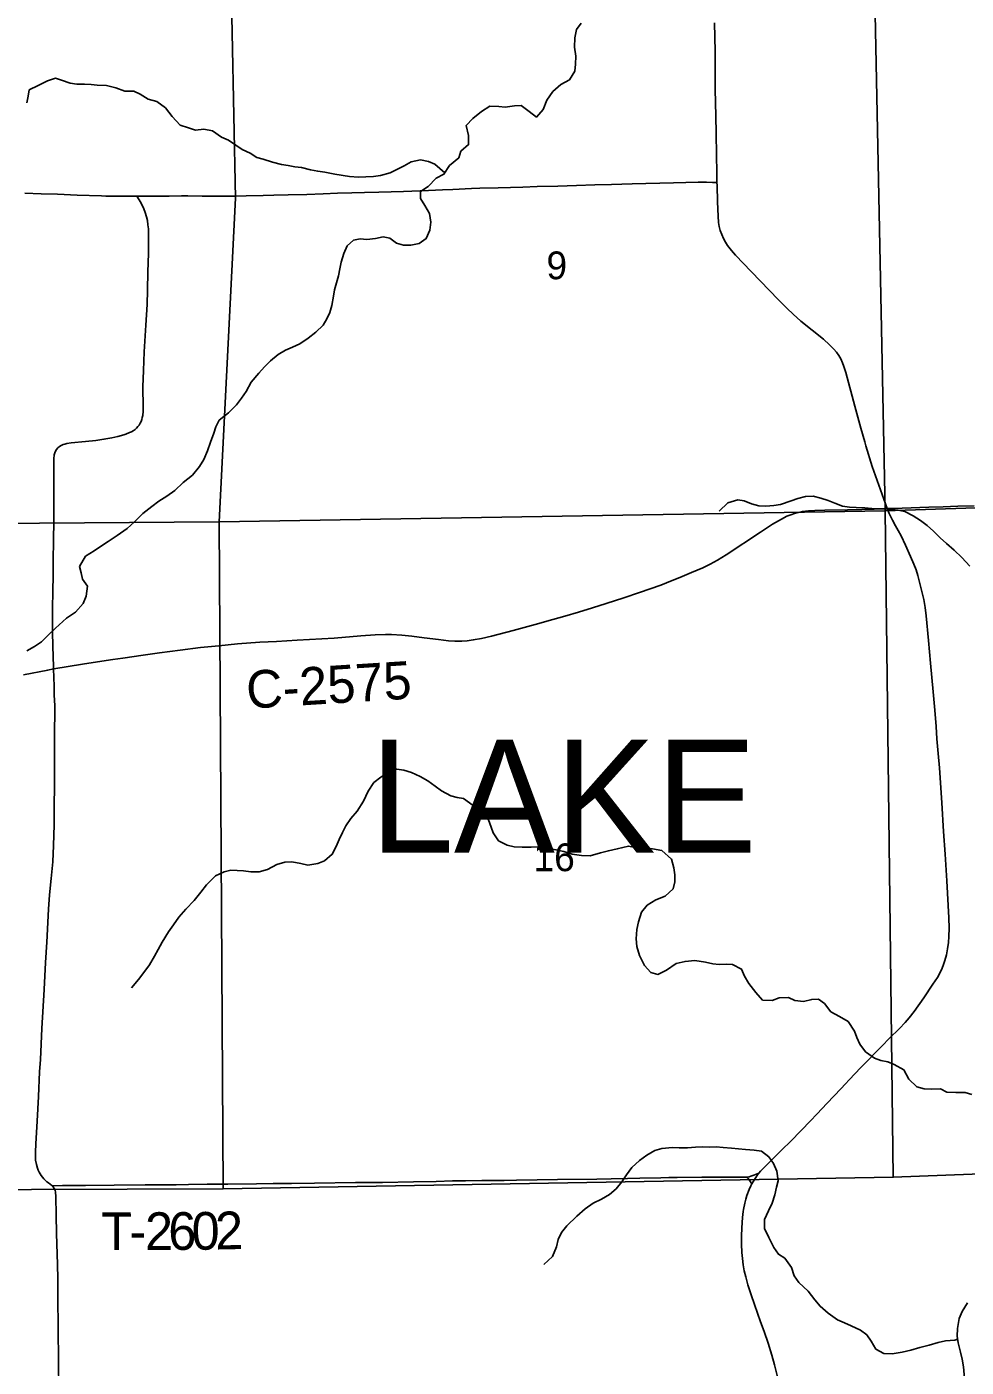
# Model space of a CAD drawing. Extents: x 1874609 to 2204689, y 815661 to 1281160.
# Drawn here: x 2054718 to 2062191, y 975610 to 986276 of the extents above; entities that cross this region are included whole.
import ezdxf

# ---------------------------------------------------------------- set-up
doc = ezdxf.new("R2010")
doc.units = 0
for name, color, linetype in [('GM_X_County_Road', 7, 'Continuous'), ('GM_X_County_Road_Text', 7, 'Continuous'), ('GM_X_Major_River', 7, 'Continuous'), ('GM_X_Minor_River', 7, 'Continuous'), ('GM_X_Section', 7, 'Continuous'), ('GM_X_Section_Text', 7, 'Continuous'), ('GM_X_Township_Road', 7, 'Continuous'), ('GM_X_Township_Road_Text', 7, 'Continuous'), ('GM_X_Township_Text', 7, 'Continuous')]:
    doc.layers.add(name, color=color, linetype=linetype)

msp = doc.modelspace()

# ---------------------------------------------------------------- linework, layer by layer
at = {"layer": 'GM_X_County_Road'}
for points in [[(2060208, 985036), (2060207, 985128), (2060206, 985243), (2060203, 985440), (2060200, 985554), (2060197, 985685), (2060195, 985767), (2060193, 986079), (2060189, 986308)], [(2061562, 982443), (2061444, 982777), (2061394, 982941), (2061385, 982973), (2061354, 983083), (2061306, 983257), (2061234, 983526), (2061219, 983573), (2061208, 983603), (2061194, 983633), (2061178, 983661), (2061159, 983687), (2061138, 983712), (2061104, 983746), (2061055, 983790), (2060876, 983934), (2060814, 983988), (2060766, 984033), (2060697, 984103), (2060481, 984328), (2060356, 984458), (2060323, 984496), (2060293, 984535), (2060276, 984563), (2060260, 984592), (2060246, 984622), (2060235, 984654), (2060227, 984686), (2060221, 984719), (2060217, 984768), (2060213, 984883), (2060209, 985014), (2060208, 985036)], [(2054931, 981166), (2054949, 981170), (2055030, 981183), (2055176, 981206), (2055402, 981242), (2055483, 981253), (2055645, 981276), (2055774, 981294), (2055937, 981315), (2056100, 981336), (2056246, 981351), (2056393, 981365), (2056573, 981378), (2056704, 981385), (2056868, 981394), (2057162, 981412), (2057375, 981429), (2057489, 981437), (2057571, 981441), (2057620, 981440), (2057701, 981435), (2057782, 981427), (2057879, 981415), (2057993, 981400), (2058074, 981391), (2058123, 981388), (2058179, 981388), (2058221, 981391), (2058270, 981397), (2058335, 981408), (2058414, 981427), (2058588, 981473), (2058762, 981520), (2058903, 981560), (2058998, 981587), (2059108, 981619), (2059218, 981652), (2059327, 981686), (2059468, 981731), (2059592, 981774), (2059762, 981834), (2059853, 981870), (2059914, 981895), (2060005, 981933), (2060095, 981972), (2060155, 982000), (2060212, 982032), (2060282, 982075), (2060555, 982254), (2060651, 982317), (2060722, 982358), (2060765, 982381), (2060795, 982393), (2060825, 982404), (2060857, 982412), (2060888, 982419), (2060937, 982425), (2060986, 982428), (2061067, 982430), (2061247, 982432), (2061361, 982434), (2061459, 982437), (2061562, 982443)], [(2060541, 977153), (2060555, 977170), (2060583, 977200), (2060637, 977253), (2060731, 977345), (2060790, 977402), (2060881, 977496), (2060949, 977567), (2061005, 977627), (2061083, 977709), (2061196, 977827), (2061229, 977862), (2061262, 977898), (2061351, 977992), (2061408, 978050), (2061464, 978109), (2061522, 978168), (2061579, 978225), (2061661, 978305), (2061706, 978352), (2061738, 978389), (2061778, 978441), (2061853, 978548), (2061926, 978657), (2061962, 978712), (2061986, 978755), (2061999, 978784), (2062011, 978814), (2062021, 978845), (2062034, 978892), (2062043, 978940), (2062050, 978989), (2062054, 979038), (2062055, 979103), (2062053, 979185), (2062037, 979480), (2062023, 979692), (2062012, 979872), (2061998, 980102), (2061978, 980380), (2061968, 980494), (2061959, 980609), (2061952, 980707), (2061941, 980837), (2061928, 980984), (2061908, 981213), (2061892, 981393), (2061874, 981589), (2061865, 981654), (2061853, 981718), (2061831, 981814), (2061806, 981909), (2061792, 981955), (2061775, 982001), (2061749, 982061), (2061709, 982151), (2061674, 982225), (2061651, 982268), (2061629, 982306), (2061604, 982350), (2061578, 982404), (2061562, 982443)], [(2061562, 982443), (2061566, 982443), (2061681, 982446), (2061894, 982453), (2062009, 982457), (2062124, 982461), (2062255, 982464)], [(2054692, 981119), (2054885, 981157), (2054931, 981166)], [(2060486, 977068), (2060512, 977112), (2060537, 977149), (2060541, 977153)], [(2060690, 975533), (2060667, 975628), (2060646, 975707), (2060617, 975801), (2060584, 975893), (2060556, 975970), (2060507, 976109), (2060480, 976187), (2060455, 976265), (2060438, 976328), (2060426, 976376), (2060417, 976425), (2060411, 976474), (2060407, 976523), (2060405, 976589), (2060405, 976654), (2060407, 976720), (2060413, 976802), (2060417, 976850), (2060419, 976866), (2060429, 976914), (2060437, 976946), (2060447, 976977), (2060465, 977023), (2060478, 977054), (2060486, 977068)]]:
    msp.add_lwpolyline(points, dxfattribs=at)
at = {"layer": 'GM_X_Major_River'}
msp.add_lwpolyline([(2062203, 976122), (2062158, 976054), (2062136, 975997), (2062122, 975919), (2062120, 975857), (2062127, 975803), (2062147, 975729), (2062159, 975673), (2062169, 975613), (2062176, 975553), (2062180, 975475), (2062180, 975423), (2062177, 975358), (2062173, 975302), (2062153, 975182), (2062146, 975114), (2062142, 975042), (2062142, 974968), (2062162, 974911), (2062193, 974837)], dxfattribs=at)
at = {"layer": 'GM_X_Minor_River'}
for points in [[(2059127, 986305), (2059092, 986255), (2059078, 986189), (2059074, 986113), (2059085, 986043), (2059083, 985979), (2059077, 985923), (2059035, 985854), (2058967, 985818), (2058904, 985760), (2058854, 985691), (2058826, 985617), (2058772, 985557), (2058714, 985601), (2058650, 985650), (2058598, 985646), (2058524, 985636), (2058472, 985642), (2058402, 985645), (2058336, 985603), (2058266, 985545), (2058214, 985490), (2058231, 985410), (2058233, 985338), (2058171, 985286), (2058155, 985234), (2058080, 985171), (2058036, 985103), (2057976, 985071), (2057912, 985006), (2057850, 984964), (2057851, 984910), (2057885, 984854), (2057921, 984790), (2057933, 984722), (2057924, 984658), (2057896, 984590), (2057840, 984551), (2057772, 984539), (2057714, 984537), (2057658, 984553), (2057606, 984594), (2057554, 984604), (2057492, 984592), (2057422, 984584), (2057370, 984588)], [(2058044, 985115), (2057964, 985183), (2057913, 985205), (2057849, 985217), (2057775, 985202), (2057721, 985170), (2057668, 985142), (2057608, 985115), (2057532, 985093), (2057476, 985085), (2057414, 985083), (2057358, 985080), (2057286, 985084), (2057169, 985104), (2057089, 985118), (2057033, 985127), (2056975, 985137), (2056903, 985155), (2056851, 985161), (2056797, 985171), (2056745, 985180), (2056673, 985200), (2056599, 985222), (2056548, 985236), (2056494, 985270), (2056432, 985299), (2056380, 985333), (2056322, 985373), (2056268, 985397), (2056195, 985447), (2056127, 985461), (2056061, 985454), (2056005, 985472), (2055937, 985494), (2055875, 985562), (2055822, 985630), (2055752, 985682), (2055684, 985701), (2055620, 985741), (2055570, 985763), (2055498, 985763), (2055426, 985789), (2055353, 985808), (2055279, 985812), (2055229, 985816), (2055177, 985820), (2055115, 985819), (2055063, 985827), (2054995, 985851), (2054945, 985867), (2054883, 985847), (2054809, 985810), (2054737, 985774), (2054729, 985724), (2054718, 985670)], [(2057370, 984588), (2057318, 984579), (2057266, 984533), (2057240, 984473), (2057218, 984403), (2057207, 984349), (2057197, 984294), (2057181, 984238), (2057167, 984182), (2057157, 984132), (2057144, 984058), (2057128, 984002), (2057104, 983951), (2057076, 983901), (2057017, 983847), (2056957, 983797), (2056891, 983752), (2056831, 983726), (2056775, 983702), (2056717, 983669), (2056657, 983619), (2056609, 983569), (2056564, 983519), (2056504, 983448), (2056464, 983374), (2056426, 983322), (2056387, 983267), (2056323, 983205), (2056249, 983145), (2056223, 983094), (2056205, 983042), (2056180, 982970), (2056156, 982902), (2056126, 982834), (2056091, 982777), (2056035, 982709), (2055963, 982649), (2055895, 982586), (2055831, 982542), (2055769, 982500), (2055712, 982459), (2055642, 982403), (2055576, 982337), (2055516, 982284), (2055438, 982228), (2055365, 982180), (2055313, 982145), (2055253, 982107), (2055185, 982063), (2055137, 981982), (2055150, 981930), (2055160, 981880), (2055202, 981824), (2055190, 981746), (2055167, 981688), (2055105, 981617), (2055033, 981569), (2054947, 981491), (2054887, 981434), (2054834, 981382), (2054778, 981346), (2054718, 981311)], [(2062221, 981983), (2062157, 982053), (2062095, 982111), (2062034, 982165), (2061984, 982210), (2061932, 982262), (2061880, 982308), (2061827, 982348), (2061769, 982384), (2061703, 982418), (2061649, 982430), (2061575, 982437), (2061513, 982439), (2061441, 982443), (2061385, 982447), (2061317, 982450), (2061263, 982454), (2061207, 982462), (2061146, 982484), (2061094, 982506), (2061036, 982526), (2060974, 982541), (2060912, 982539), (2060852, 982523), (2060798, 982503), (2060714, 982476), (2060662, 982468), (2060598, 982462), (2060542, 982464), (2060484, 982479), (2060426, 982503), (2060374, 982513), (2060296, 982489), (2060226, 982422)], [(2058091, 980156), (2058016, 980196), (2057966, 980234), (2057908, 980276), (2057848, 980311), (2057778, 980341), (2057717, 980361), (2057661, 980369), (2057597, 980348), (2057534, 980306), (2057480, 980262), (2057434, 980194), (2057396, 980113), (2057345, 980035), (2057297, 979975), (2057257, 979918), (2057229, 979866), (2057203, 979810), (2057180, 979754), (2057148, 979692), (2057086, 979639), (2057032, 979619), (2056954, 979605), (2056898, 979618), (2056826, 979632), (2056770, 979628), (2056708, 979610), (2056632, 979571), (2056566, 979553), (2056500, 979553), (2056442, 979559), (2056392, 979562), (2056342, 979564), (2056288, 979552), (2056220, 979520), (2056148, 979447), (2056103, 979389), (2056049, 979323), (2055983, 979254), (2055927, 979190), (2055886, 979130), (2055844, 979073), (2055794, 978993), (2055762, 978933), (2055735, 978881), (2055693, 978812), (2055649, 978752), (2055607, 978696), (2055552, 978628)], [(2062237, 977779), (2062184, 977797), (2062110, 977795), (2062038, 977798), (2061988, 977824), (2061916, 977822), (2061858, 977824), (2061798, 977842), (2061736, 977903), (2061695, 977977), (2061619, 978019), (2061567, 978039), (2061513, 978051), (2061461, 978069), (2061391, 978119), (2061344, 978181), (2061320, 978233), (2061302, 978283), (2061252, 978360), (2061183, 978400), (2061115, 978438), (2061065, 978504), (2061015, 978538), (2060963, 978536), (2060897, 978521), (2060827, 978529), (2060777, 978551), (2060703, 978549), (2060647, 978527), (2060571, 978530), (2060518, 978592), (2060462, 978662), (2060428, 978722), (2060405, 978778), (2060333, 978814), (2060281, 978816), (2060227, 978815), (2060177, 978819), (2060117, 978833), (2060033, 978847), (2059955, 978839), (2059885, 978822), (2059807, 978770), (2059737, 978736), (2059683, 978751), (2059633, 978807), (2059591, 978887), (2059570, 978957), (2059566, 979019), (2059572, 979092), (2059585, 979154), (2059609, 979230), (2059653, 979286), (2059721, 979329), (2059797, 979359), (2059861, 979417), (2059874, 979471), (2059874, 979528), (2059866, 979584), (2059846, 979652), (2059769, 979721), (2059695, 979735), (2059645, 979737), (2059569, 979743), (2059505, 979757), (2059415, 979734), (2059345, 979720), (2059283, 979704), (2059199, 979679), (2059131, 979681), (2059057, 979693), (2058989, 979713), (2058927, 979728), (2058851, 979742), (2058789, 979750), (2058731, 979748), (2058659, 979747), (2058596, 979751), (2058540, 979763), (2058470, 979799), (2058428, 979863), (2058398, 979945), (2058375, 980003), (2058321, 980063), (2058269, 980080), (2058193, 980134), (2058141, 980142), (2058091, 980156)], [(2062123, 975833), (2062101, 975825), (2062027, 975819), (2061967, 975806), (2061897, 975786), (2061823, 975766), (2061751, 975745), (2061681, 975729), (2061603, 975717), (2061535, 975719), (2061473, 975754), (2061436, 975816), (2061400, 975868), (2061350, 975906), (2061276, 975940), (2061224, 975962), (2061167, 975988), (2061093, 976040), (2061029, 976095), (2060987, 976147), (2060934, 976215), (2060860, 976283), (2060822, 976337), (2060801, 976403), (2060749, 976477), (2060697, 976509), (2060661, 976563), (2060622, 976641), (2060588, 976713), (2060588, 976785), (2060618, 976853), (2060647, 976914), (2060669, 976982), (2060683, 977042), (2060695, 977092), (2060684, 977170), (2060658, 977232), (2060620, 977284), (2060562, 977330), (2060505, 977338), (2060435, 977342), (2060381, 977347), (2060325, 977353), (2060257, 977359), (2060203, 977363), (2060153, 977362), (2060097, 977364), (2060037, 977360), (2059973, 977356), (2059907, 977356), (2059855, 977359), (2059769, 977351), (2059715, 977335), (2059651, 977298), (2059591, 977256), (2059530, 977200), (2059488, 977142), (2059452, 977085), (2059406, 977029), (2059354, 976983), (2059290, 976948), (2059225, 976916), (2059159, 976870), (2059093, 976813), (2059013, 976735), (2058971, 976683), (2058944, 976625), (2058932, 976568), (2058900, 976492), (2058830, 976426)]]:
    msp.add_lwpolyline(points, dxfattribs=at)
at = {"layer": 'GM_X_Section'}
for points in [[(2061440, 987697), (2066614, 987971), (2066679, 982593), (2061547, 982423)], [(2056326, 987545), (2061440, 987697), (2061547, 982423), (2056248, 982336), (2056379, 984912)], [(2050843, 987600), (2056326, 987545), (2056379, 984912), (2056248, 982336), (2050888, 982296)], [(2061547, 982423), (2066679, 982593), (2066781, 977319), (2061611, 977121)], [(2056248, 982336), (2061547, 982423), (2061611, 977121), (2056279, 977030)], [(2050888, 982296), (2056248, 982336), (2056279, 977030), (2050936, 977011)]]:
    msp.add_lwpolyline(points, close=True, dxfattribs=at)
at = {"layer": 'GM_X_Township_Road'}
for points in [[(2055594, 984929), (2055607, 984929), (2055689, 984928), (2055851, 984929), (2055949, 984930), (2055998, 984930), (2056112, 984929), (2056267, 984929), (2056376, 984928), (2056462, 984930), (2056599, 984934), (2056683, 984935), (2056798, 984938), (2056945, 984942), (2057076, 984947), (2057191, 984951), (2057305, 984955), (2057404, 984958), (2057518, 984961), (2057616, 984963), (2057714, 984966), (2057780, 984968), (2057915, 984973), (2058026, 984978), (2058107, 984981), (2058255, 984989), (2058321, 984992), (2058468, 984994), (2058665, 985001), (2058779, 985004), (2058943, 985009), (2059091, 985014), (2059238, 985018), (2059370, 985022), (2059534, 985026), (2059862, 985034), (2060058, 985039), (2060124, 985039), (2060173, 985038), (2060208, 985036)], [(2054703, 984953), (2054832, 984948), (2054962, 984943), (2055119, 984937), (2055313, 984930), (2055346, 984929), (2055411, 984929), (2055509, 984929), (2055594, 984929)], [(2054931, 981166), (2054927, 981282), (2054926, 981331), (2054924, 981363), (2054923, 981445), (2054923, 981527), (2054923, 981642), (2054925, 981790), (2054927, 981904), (2054929, 982019), (2054931, 982200), (2054932, 982333), (2054933, 982435), (2054933, 982509), (2054934, 982576), (2054932, 982642), (2054932, 982707), (2054932, 982772), (2054933, 982837), (2054936, 982869), (2054941, 982885), (2054946, 982900), (2054955, 982913), (2054965, 982926), (2054977, 982936), (2054991, 982945), (2055006, 982951), (2055021, 982956), (2055037, 982960), (2055070, 982965), (2055184, 982975), (2055266, 982985), (2055331, 982994), (2055395, 983006), (2055443, 983017), (2055490, 983030), (2055506, 983035), (2055536, 983047), (2055551, 983054), (2055565, 983062), (2055579, 983072), (2055591, 983083), (2055602, 983095), (2055612, 983107), (2055621, 983121), (2055628, 983136), (2055633, 983152), (2055637, 983168), (2055640, 983184), (2055643, 983217), (2055644, 983266), (2055644, 983298), (2055642, 983363), (2055642, 983379), (2055642, 983411), (2055647, 983542), (2055653, 983690), (2055665, 983902), (2055675, 984066), (2055679, 984180), (2055682, 984327), (2055686, 984473), (2055686, 984538), (2055687, 984570), (2055687, 984620), (2055686, 984669), (2055682, 984701), (2055677, 984734), (2055670, 984765), (2055660, 984797), (2055648, 984827), (2055635, 984856), (2055619, 984885), (2055611, 984899), (2055594, 984929)], [(2054922, 977052), (2054917, 977057), (2054890, 977076), (2054877, 977086), (2054865, 977097), (2054853, 977109), (2054842, 977121), (2054833, 977135), (2054824, 977148), (2054816, 977163), (2054809, 977178), (2054803, 977193), (2054794, 977224), (2054788, 977257), (2054786, 977289), (2054786, 977322), (2054790, 977387), (2054801, 977568), (2054810, 977764), (2054820, 977961), (2054826, 978059), (2054838, 978305), (2054856, 978616), (2054868, 978829), (2054877, 978993), (2054891, 979255), (2054899, 979370), (2054911, 979500), (2054924, 979631), (2054930, 979762), (2054936, 979926), (2054937, 980057), (2054938, 980254), (2054938, 980401), (2054939, 980613), (2054940, 980875), (2054937, 980958), (2054935, 981029), (2054931, 981166)], [(2054922, 977052), (2055003, 977055), (2055053, 977057), (2055184, 977057), (2055414, 977058), (2055660, 977061), (2055906, 977062), (2056005, 977065), (2056152, 977066), (2056317, 977067), (2056546, 977070), (2056678, 977071), (2056825, 977073), (2057006, 977075), (2057334, 977079), (2057547, 977081), (2057794, 977085), (2057974, 977088), (2058105, 977092), (2058209, 977093), (2058338, 977095), (2058422, 977095), (2058515, 977096), (2058613, 977097), (2058777, 977100), (2058941, 977103), (2059252, 977107), (2059367, 977108), (2059498, 977111), (2059596, 977113), (2059761, 977117), (2059826, 977119), (2059892, 977120), (2060088, 977123), (2060301, 977123), (2060350, 977122), (2060448, 977122)], [(2060448, 977122), (2060448, 977122), (2060464, 977125), (2060479, 977130), (2060503, 977139), (2060541, 977153)], [(2060448, 977122), (2060452, 977117), (2060457, 977112), (2060465, 977102), (2060486, 977068)], [(2054974, 975460), (2054971, 975624), (2054970, 975706), (2054968, 975870), (2054968, 975952), (2054966, 976133), (2054964, 976313), (2054962, 976428), (2054958, 976591), (2054955, 976673), (2054952, 976821), (2054948, 976969), (2054946, 977002), (2054943, 977018), (2054937, 977033), (2054929, 977046), (2054922, 977052)]]:
    msp.add_lwpolyline(points, dxfattribs=at)

# ---------------------------------------------------------------- texts
at = {"layer": 'GM_X_County_Road_Text'}
msp.add_text('C-2575', height=300, rotation=3.5787, dxfattribs=at).set_placement((2056473, 980849))
at = {"layer": 'GM_X_Section_Text'}
for s, p in [('9', (2058852, 984267)), ('16', (2058749, 979557))]:
    msp.add_text(s, height=221, rotation=0, dxfattribs=at).set_placement(p)
at = {"layer": 'GM_X_Township_Road_Text'}
for s, rotation, p in [('T', 0.2443, (2055311, 976541)), ('2', 0.2592, (2055659, 976542)), ('6', 0.3078, (2055844, 976543)), ('0', 0.4521, (2056030, 976544)), ('2', 1.169, (2056219, 976546)), ('-', 0.2557, (2055536, 976542))]:
    msp.add_text(s, height=300, rotation=rotation, dxfattribs=at).set_placement(p)
at = {"layer": 'GM_X_Township_Text'}
msp.add_text('LAKE', height=900, rotation=0, dxfattribs=at).set_placement((2057447, 979704))

doc.saveas('drawing.dxf')
